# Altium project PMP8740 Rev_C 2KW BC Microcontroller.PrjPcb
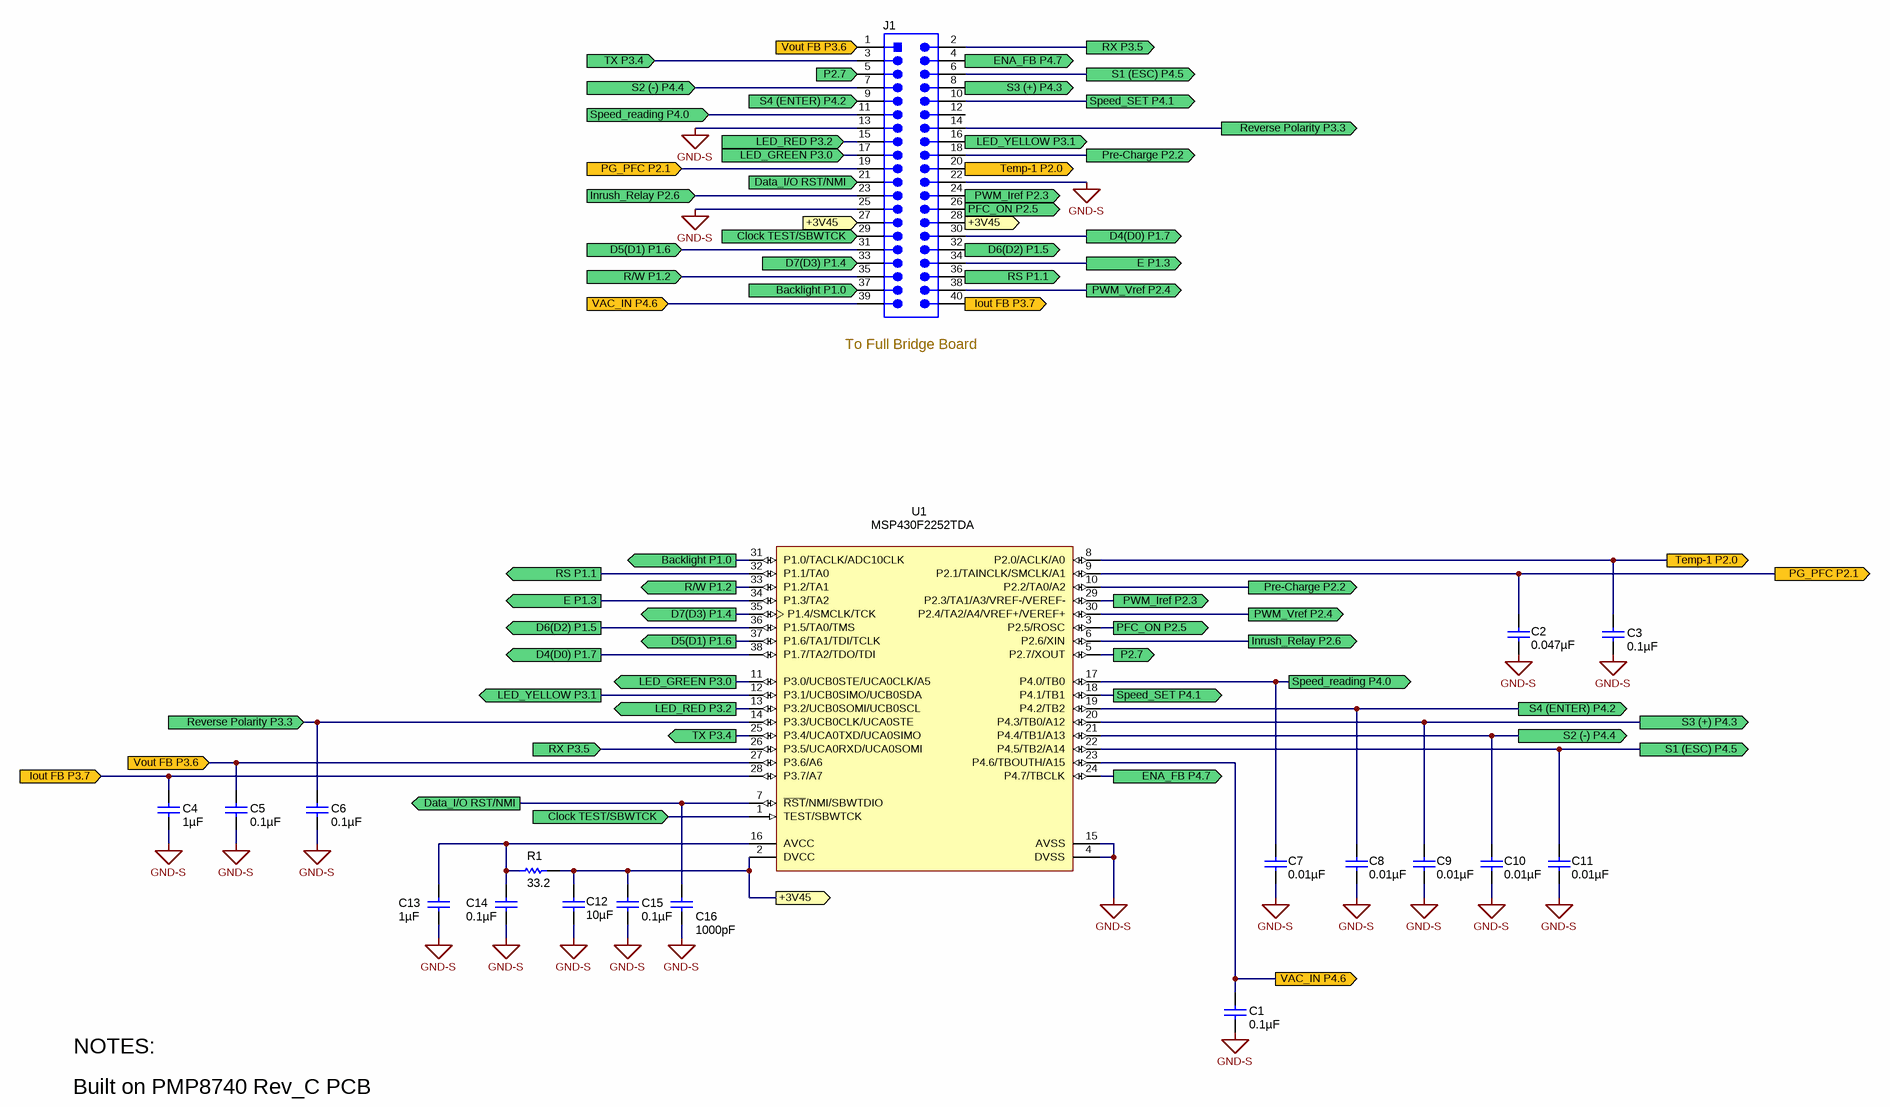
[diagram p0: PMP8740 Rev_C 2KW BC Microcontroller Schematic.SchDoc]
TechSupport: http://www.ti.com/support; SCH_Rev: C; PRJ_Title: 2KW Battery Charger; PRJ_Number: PMP8740; PRJ_Engineer: R. Scibilia; PRJ_Customer: Public Release; PCB_Rev: C; PCB_Layout: R. Scibilia; CopyrightYear: 2014
1 sheet, 19 parts. Net scope: flat (ports and power ports of the same name join across sheets).
Board file: PMP8740 Rev_C Microcontroller PCB.PcbDoc

## Sheet PMP8740 Rev_C 2KW BC Microcontroller Schematic.SchDoc: Microcontroller
size 431 x 279 mm; Date: Not shown in title block; ApprovedBy: Not shown in title block; CheckedBy: Not shown in title block; Author: Not shown in title block; CompanyName: Not shown in title block; DrawnBy: R. Scibilia; Engineer: Not shown in title block; Organization: Not shown in title block; Address1: Not shown in title block; Address2: Not shown in title block; Address3: Not shown in title block; Address4: Not shown in title block; DocumentNumber: 1; Revision: Use project parameter SCH_Rev; SheetNumber: 1; SheetTotal: 1; PageSetup: Record=PageOptions|CenterHorizontal=True|CenterVertical=True|PrintScale=1.00|XCorrection=1.00|YCorrection=1.00|PrintKind=0|BorderSize=5000000|LeftOffset=0|BottomOffset=0|Orientation=2|PaperLength=1000|PaperWidth=1000|Scale=100|PaperSource=15|PrintQuality=600|MediaType=1|DitherType=10|PaperKind=Letter|PrintScaleMode=1

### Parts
C1  ValueDisplayed: 0.1µF  [0603]  (hidden comment: C1608X7R1H104K)
C2  ValueDisplayed: 0.047µF  [0603]  (hidden comment: C1608X7R1H473K)
C3  ValueDisplayed: 0.1µF  [0603]  (hidden comment: C1608X7R1H104K)
C4  ValueDisplayed: 1µF  [0603]  (hidden comment: C1608X7R1E105K080AB)
C5  ValueDisplayed: 0.1µF  [0603]  (hidden comment: C1608X7R1H104K)
C6  ValueDisplayed: 0.1µF  [0603]  (hidden comment: C1608X7R1H104K)
C7  ValueDisplayed: 0.01µF  [0603]  (hidden comment: C1608X7R1H103K)
C8  ValueDisplayed: 0.01µF  [0603]  (hidden comment: C1608X7R1H103K)
C9  ValueDisplayed: 0.01µF  [0603]  (hidden comment: C1608X7R1H103K)
C10  ValueDisplayed: 0.01µF  [0603]  (hidden comment: C1608X7R1H103K)
C11  ValueDisplayed: 0.01µF  [0603]  (hidden comment: C1608X7R1H103K)
C12  ValueDisplayed: 10µF  [1206]  (hidden comment: C3216X7R1A106M)
C13  ValueDisplayed: 1µF  [0603]  (hidden comment: C1608X7R1E105K080AB)
C14  ValueDisplayed: 0.1µF  [0603]  (hidden comment: C1608X7R1H104K)
C15  ValueDisplayed: 0.1µF  [0603]  (hidden comment: C1608X7R1H104K)
C16  ValueDisplayed: 1000pF  [0603]  (hidden comment: C1608C0G1H102J)
J1  NPPN202FJFN-RC  [HEADER_NPPN202FJFN-RC]  (value not drawn)
R1  value 33.2  [0603]  (hidden comment: CRCW060333R2FKEA)
U1  MSP430F2252TDA  [DA0038A_N]

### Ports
+3V45, Backlight P1.0, Clock TEST/SBWTCK, D4(D0) P1.7, D5(D1) P1.6, D6(D2) P1.5, D7(D3) P1.4, Data_I/O RST/NMI, E P1.3, ENA_FB P4.7, Inrush_Relay P2.6, Iout FB P3.7, LED_GREEN P3.0, LED_RED P3.2, LED_YELLOW P3.1, P2.7, PFC_ON P2.5, PG_PFC P2.1, Pre-Charge P2.2, PWM_Iref P2.3, PWM_Vref P2.4, R/W P1.2, Reverse Polarity P3.3, RS P1.1, RX P3.5, S1 (ESC) P4.5, S2 (-) P4.4, S3 (+) P4.3, S4 (ENTER) P4.2, Speed_reading P4.0, Speed_SET P4.1, Temp-1 P2.0, TX P3.4, VAC_IN P4.6, Vout FB P3.6

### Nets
GND-S: C1.2 C2.2 C3.2 C4.2 C5.2 C6.2 C7.2 C8.2 C9.2 C10.2 C11.2 C12.2 C13.2 C14.2 C15.2 C16.2 J1.13 J1.22 J1.25 U1.4(DVSS) U1.15(AVSS)
+3V45: C12.1 C15.1 J1.27 J1.28 R1.2 U1.2(DVCC) ; port +3V45
Backlight P1.0: J1.37 U1.31(P1.0/TACLK/ADC10CLK) ; port Backlight P1.0
Clock TEST/SBWTCK: J1.29 U1.1(TEST/SBWTCK) ; port Clock TEST/SBWTCK
D4(D0) P1.7: J1.30 U1.38(P1.7/TA2/TDO/TDI) ; port D4(D0) P1.7
D5(D1) P1.6: J1.31 U1.37(P1.6/TA1/TDI/TCLK) ; port D5(D1) P1.6
D6(D2) P1.5: J1.32 U1.36(P1.5/TA0/TMS) ; port D6(D2) P1.5
D7(D3) P1.4: J1.33 U1.35(P1.4/SMCLK/TCK) ; port D7(D3) P1.4
Data_I/O RST/NMI: C16.1 J1.21 U1.7(~{RST}/NMI/SBWTDIO) ; port Data_I/O RST/NMI
E P1.3: J1.34 U1.34(P1.3/TA2) ; port E P1.3
ENA_FB P4.7: J1.4 U1.24(P4.7/TBCLK) ; port ENA_FB P4.7
Inrush_Relay P2.6: J1.23 U1.6(P2.6/XIN) ; port Inrush_Relay P2.6
Iout FB P3.7: C4.1 J1.40 U1.28(P3.7/A7) ; port Iout FB P3.7
LED_GREEN P3.0: J1.17 U1.11(P3.0/UCB0STE/UCA0CLK/A5) ; port LED_GREEN P3.0
LED_RED P3.2: J1.15 U1.13(P3.2/UCB0SOMI/UCB0SCL) ; port LED_RED P3.2
LED_YELLOW P3.1: J1.16 U1.12(P3.1/UCB0SIMO/UCB0SDA) ; port LED_YELLOW P3.1
P2.7: J1.5 U1.5(P2.7/XOUT) ; port P2.7
PFC_ON P2.5: J1.26 U1.3(P2.5/ROSC) ; port PFC_ON P2.5
PG_PFC P2.1: C2.1 J1.19 U1.9(P2.1/TAINCLK/SMCLK/A1) ; port PG_PFC P2.1
Pre-Charge P2.2: J1.18 U1.10(P2.2/TA0/A2) ; port Pre-Charge P2.2
PWM_Iref P2.3: J1.24 U1.29(P2.3/TA1/A3/VREF-/VEREF-) ; port PWM_Iref P2.3
PWM_Vref P2.4: J1.38 U1.30(P2.4/TA2/A4/VREF+/VEREF+) ; port PWM_Vref P2.4
R/W P1.2: J1.35 U1.33(P1.2/TA1) ; port R/W P1.2
Reverse Polarity P3.3: C6.1 J1.14 U1.14(P3.3/UCB0CLK/UCA0STE) ; port Reverse Polarity P3.3
RS P1.1: J1.36 U1.32(P1.1/TA0) ; port RS P1.1
RX P3.5: J1.2 U1.26(P3.5/UCA0RXD/UCA0SOMI) ; port RX P3.5
S1 (ESC) P4.5: C11.1 J1.6 U1.22(P4.5/TB2/A14) ; port S1 (ESC) P4.5
S2 (-) P4.4: C10.1 J1.7 U1.21(P4.4/TB1/A13) ; port S2 (-) P4.4
S3 (+) P4.3: C9.1 J1.8 U1.20(P4.3/TB0/A12) ; port S3 (+) P4.3
S4 (ENTER) P4.2: C8.1 J1.9 U1.19(P4.2/TB2) ; port S4 (ENTER) P4.2
Speed_reading P4.0: C7.1 J1.11 U1.17(P4.0/TB0) ; port Speed_reading P4.0
Speed_SET P4.1: J1.10 U1.18(P4.1/TB1) ; port Speed_SET P4.1
Temp-1 P2.0: C3.1 J1.20 U1.8(P2.0/ACLK/A0) ; port Temp-1 P2.0
TX P3.4: J1.3 U1.25(P3.4/UCA0TXD/UCA0SIMO) ; port TX P3.4
VAC_IN P4.6: C1.1 J1.39 U1.23(P4.6/TBOUTH/A15) ; port VAC_IN P4.6
Vout FB P3.6: C5.1 J1.1 U1.27(P3.6/A6) ; port Vout FB P3.6
NetC13_1: C13.1 C14.1 R1.1 U1.16(AVCC)

Not connected (* = marked no-connect by the designer): J1 12

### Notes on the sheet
- (near J1) To Full Bridge Board
- NOTES:
- Built on PMP8740 Rev_C PCB

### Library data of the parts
C1 C3 C5 C6 C14 C15 = C1608X7R1H104K: CAP, CERM, 0.1uF, 50V, +/-10%, X7R, 0603; Manufacturer: TDK; Polarized: N; CompType: Capacitor; U/M: EA; Cap_F: 0.0000001; Tolerance_%: 10; ESR_Ohm: 0.017; Value1: 0.017 ohm; VDC_V: 50; TaMin_C: -55; TaMax_C: 125
C2 = C1608X7R1H473K: CAP, CERM, 0.047 µF, 50 V, +/- 10%, X7R, 0603; Manufacturer: TDK; Polarized: N; CompType: Capacitor; Value: 0.047uF; U/M: EA; Cap_F: 0.000000047; Tolerance_%: 10; ESR_ohm: 0.0234; Value1: 0.0234 ohm; VDC_V: 50; Value2: 50V; TaMin_C: -55; TaMax_C: 125
C4 C13 = C1608X7R1E105K080AB: CAP, CERM, 1uF, 25V, +/-10%, X7R, 0603; Manufacturer: TDK; Polarized: N; CompType: Capacitor; U/M: EA; Cap_F: 0.000001; Tolerance_%: 10; Value1: Unknown; VDC_V: 25; TaMin_C: -55; TaMax_C: 125
C7-C11 = C1608X7R1H103K: CAP, CERM, 0.01uF, 50V, +/-10%, X7R, 0603; Manufacturer: TDK; Polarized: N; CompType: Capacitor; U/M: EA; Cap_F: 0.00000001; Tolerance_%: 10; ESR_Ohm: 0.0539; Value1: 0.0539 ohm; VDC_V: 50; TaMin_C: -55; TaMax_C: 125
C12 = C3216X7R1A106M: CAP, CERM, 10uF, 10V, +/-20%, X7R, 1206; Manufacturer: TDK; Polarized: N; CompType: Capacitor; U/M: EA; Cap_F: 0.00001; Tolerance_%: 20; ESR_Ohm: 0.0046; Value1: 0.0046 ohm; VDC_V: 10; TaMin_C: -55; TaMax_C: 125
C16 = C1608C0G1H102J: CAP, CERM, 1000pF, 50V, +/-5%, C0G/NP0, 0603; Manufacturer: TDK; Polarized: N; CompType: Capacitor; U/M: EA; Cap_F: 0.000000001; Tolerance_%: 5; ESR_Ohm: 0.0563; Value1: 0.0563 ohm; VDC_V: 50; TaMin_C: -55; TaMax_C: 125
J1 = NPPN202FJFN-RC: Receptacle, 2mm, 20x2, R/A, TH; Manufacturer: Sullins Connector Solutions; SymbolCreator: a0412235; CompType: Header; U/M: EA
R1 = CRCW060333R2FKEA: RES, 33.2 ohm, 1%, 0.1W, 0603; Manufacturer: Vishay-Dale; CompType: Resistor; Value_Code: 33R2; Tolerance_%: 1; Power_W: 0.1; VDC_V: 75; TempCo: 100 ppm/C; EIA_Code: E96; U/M: EA
U1 = MSP430F2252TDA: MIXED SIGNAL MICROCONTROLLER, DA0038A; Alternate Manufacturer: None; Manufacturer: Texas Instruments; ADC: 10-bit SAR; ADC Channels: 12; Brown Out Reset: Yes; Eco-Plan: Green (RoHS & no Sb/Br); Flash(KB): 16; GPIO: 32; SRAM(B): 512; SubFamily: 2 Series, Extended Temp; Timers - 16-bit: 2; USCI_A (UART/LIN/IrDA/SPI): 1; SymbolCreator: Altium/a0412235; CompType: IC; U/M: EA

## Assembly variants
001: not fitted FID1 FID2 FID3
